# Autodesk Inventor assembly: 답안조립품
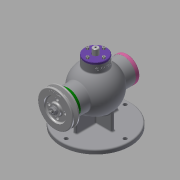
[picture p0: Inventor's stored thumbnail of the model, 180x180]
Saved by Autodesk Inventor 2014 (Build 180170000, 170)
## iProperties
Created: 2020-08
Part Number: 답안조립품
Document SubType Name: Assembly
Designer: kh
Author: kh
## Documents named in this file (18)
- C:\Users\kh\Desktop\700806V1022\답안조립품.iam
- C:\Users\kh\Desktop\700806V1022\본체.ipt
- C:\Users\kh\Desktop\700806V1022\V-벨트풀리.ipt
- C:\Users\kh\Desktop\700806V1022\너트 M8.ipt
- C:\Users\kh\Desktop\700806V1022\뒤커버.ipt
- C:\Users\kh\Desktop\700806V1022\멈춤링 15x1.ipt
- C:\Users\kh\Desktop\700806V1022\멈춤링 35x1.6.ipt
- 멈춤링 35x1.6.ipt
- C:\Users\kh\Desktop\700806V1022\베어링 6202.ipt
- 베어링 6202.ipt
- C:\Users\kh\Desktop\700806V1022\볼트 M4.ipt
- C:\Users\kh\Desktop\700806V1022\상부커버.ipt
- C:\Users\kh\Desktop\700806V1022\슬라이드.ipt
- C:\Users\kh\Desktop\700806V1022\앞커버.ipt
- C:\Users\kh\Desktop\700806V1022\오일 실 15 30 7.ipt
- C:\Users\kh\Desktop\700806V1022\칼라.ipt
- C:\Users\kh\Desktop\700806V1022\키 3x3x12.ipt
- C:\Users\kh\Desktop\700806V1022\편심축.ipt
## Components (1 placed, 1 different names)
1. V-벨트풀리:1 — Insert:10, Mate:2, Insert:11
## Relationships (3: Insert 2, Mate 1)
- Insert:10: V-벨트풀리:1
- Mate:2: V-벨트풀리:1
- Insert:11: V-벨트풀리:1
